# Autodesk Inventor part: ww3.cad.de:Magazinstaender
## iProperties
Created: 2005-10
Document SubType Name: Modeling
Designer: Michalik
d14: 372,963 mm
Author: Michalik
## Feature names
1. Extrusion1
2. Extrusion2
